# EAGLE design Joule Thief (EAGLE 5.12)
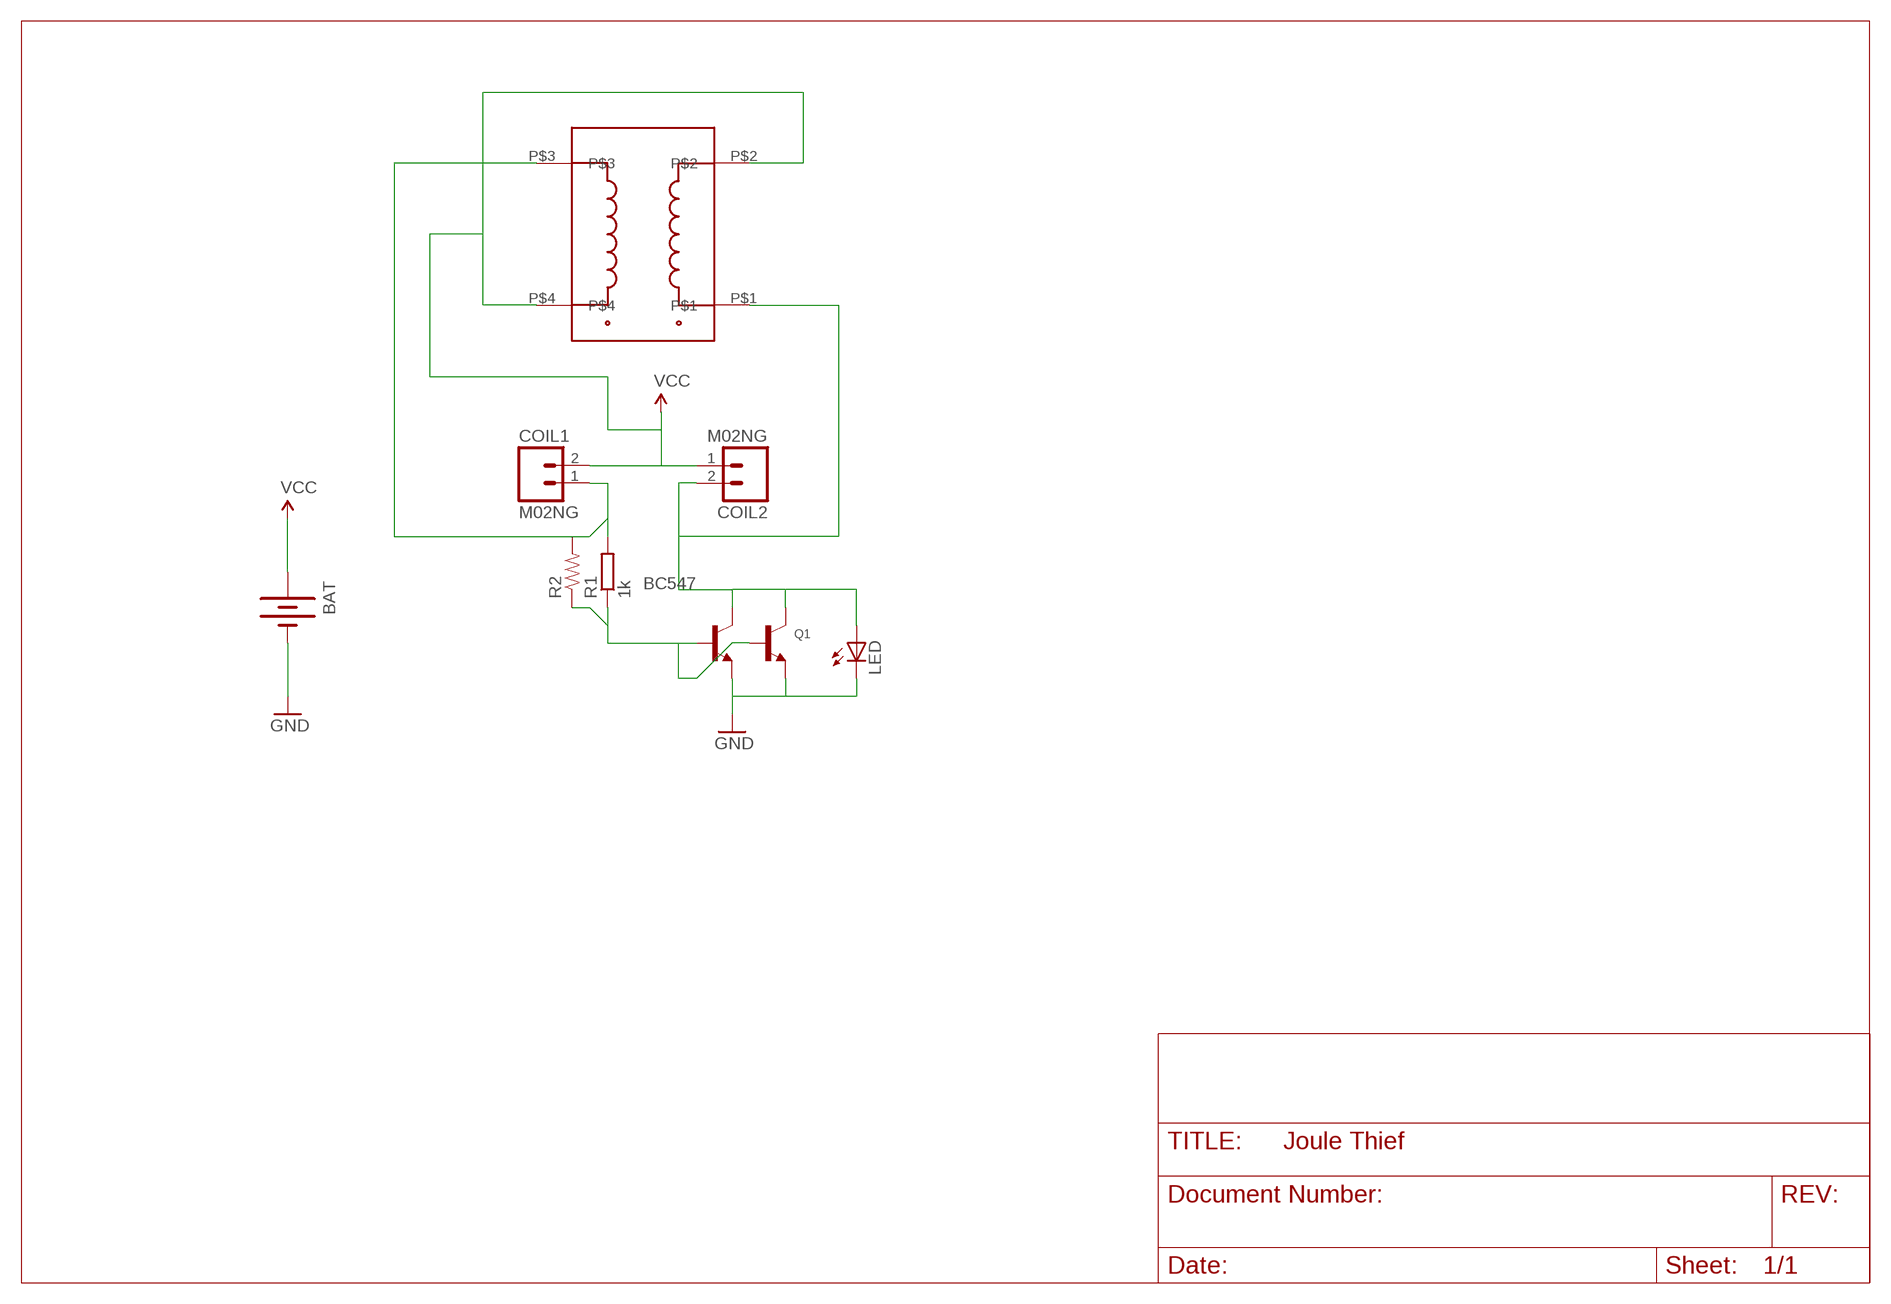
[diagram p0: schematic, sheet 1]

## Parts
BAT  BATTERYAA  [BATTERY-AA]
BC547  BC547-NPN-TO92-CBE  [TO92-CBE]
COIL1  M02NG  [1X02]
COIL2  M02NG  [1X02]
LED  LED5MM  [LED5MM]
Q1  TRANSISTOR_NPNWAVE  [SOT23-W]
R1  1k  R-EU_0309/12  [0309/12]
R2  RESISTOR1206  [1206]
U$1  SRF4532  [SRF4532]

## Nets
GND: BAT.GND@1(-) BC547.E LED.K(C) Q1.2(E)
N$1: BC547.B Q1.1(B) R1.1 R2.1
N$3: BC547.C COIL2.2 LED.A Q1.3(C) U$1.P$1
N$6: COIL1.1 R1.2 R2.2 U$1.P$3
VCC: BAT.PWR@1(+) COIL1.2 COIL2.1 U$1.P$2 U$1.P$4

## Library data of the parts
BAT = SparkFun:BATTERY: Battery Holders
BC547 = transistor:*-NPN-: NPN Transistror BF959 corrected 2008.03.06
COIL1 COIL2 = SparkFun:M02NG
LED = adafruit:LED: LED
Q1 = microbuilder:TRANSISTOR_NPN: NPN Transistor Transistor (NPN) 500mA 45V - BC817 [Digikey: 568-1631-1-ND] Transistor (NPN) 500mA 45V - BC817,215 [Mouser: 771-BC817-T/R] SOT23-R - SOT23 footprint optimised for use with solder paste and reflow ovens. SOT23-W - SOT23 footprint optimised for hand-soldering (larger pads).
R1 = resistor:R-EU_: RESISTOR, European symbol
R2 = SparkFun:RESISTOR: Resistor
U$1 = hackmeisterdk:SRF4532

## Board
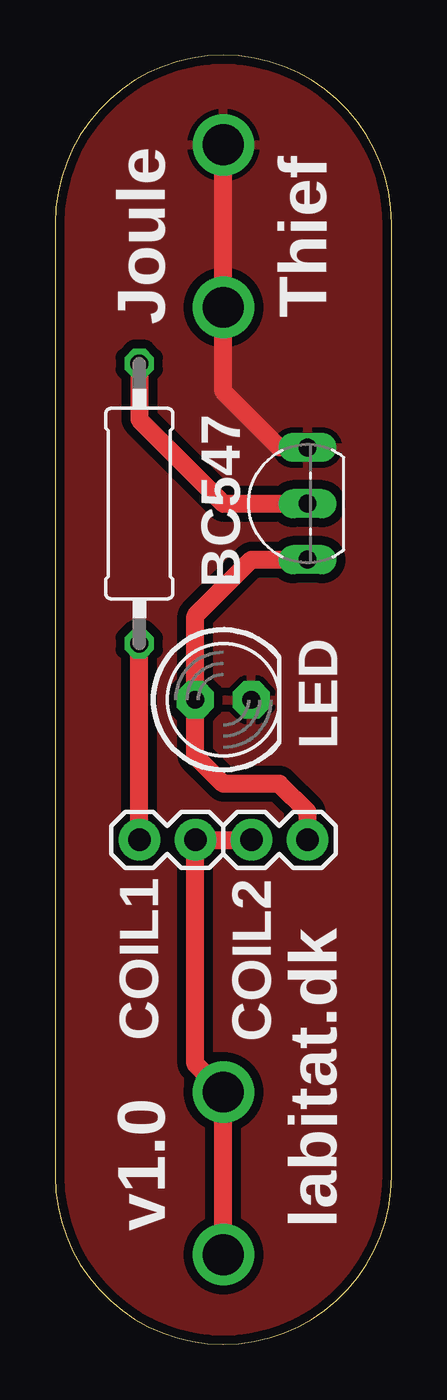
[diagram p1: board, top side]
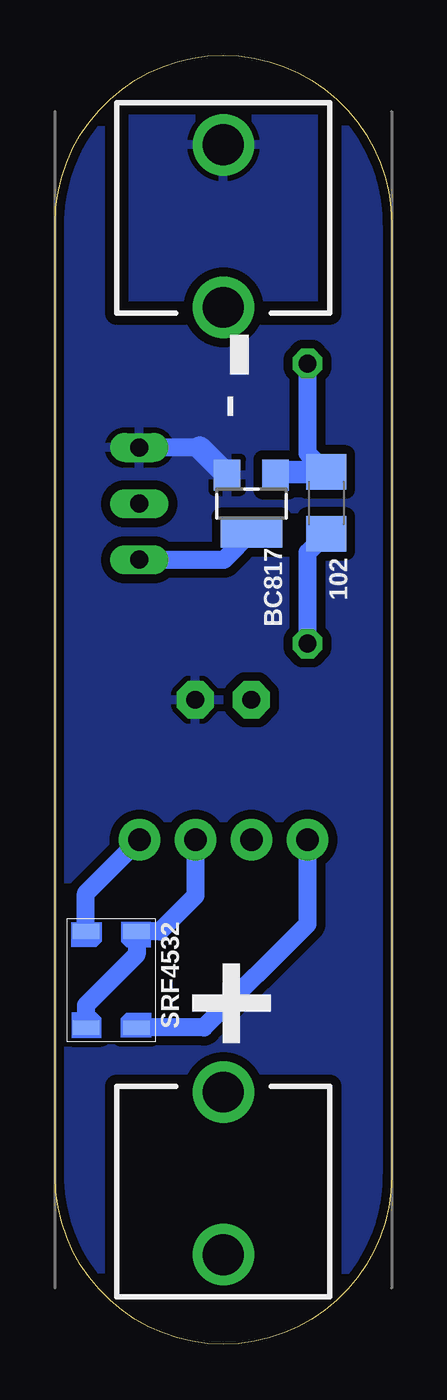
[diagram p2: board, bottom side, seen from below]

Size 15.24 x 58.42 mm. Coordinates in mm from the lower left corner, seen from the top.
Outline: 7.62,0 arc90 15.24,7.62 15.24,50.8 arc90 7.62,58.42 arc90 0,50.8 0,7.62 arc90 7.62,0
Copper layers (1*16): Top 0.035mm / dielectric 1.5mm / Bottom 0.035mm
Design rules "Fusion_eagle_rule_v1.1": minimum track width 6mil, minimum drill 12mil, track to track 6mil, track to pad 6mil, pad to pad 6mil, via to via 6mil, smd to smd 0mil, copper to edge 10mil, drill to drill 10mil, minimum pad ring 10mil, minimum via ring 6mil, stop-mask expansion 2mil, vias tented up to drill 100mil, thermal gap 10mil

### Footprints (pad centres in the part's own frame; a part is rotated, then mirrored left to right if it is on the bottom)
BATTERY-AA = drill 1.854 round: GND@1 25.146,0; GND@2 17.78,0; PWR@1 -25.146,0; PWR@2 -17.78,0
TO92-CBE = drill 0.813 long: B 0,0; C -2.54,0; E 2.54,0
1X02 = drill 1.016 pad 1.88 round: 1 0,0; 2 2.54,0
LED5MM = drill 0.813 pad 1.676 octagon: A -1.27,0; K 1.27,0
SOT23-W = smd 1.2 x 1.4: 1 -1.1,-1.3; 2 1.1,-1.3 | smd 2.8 x 1.4: 3 0,1.3
0309/12 = drill 0.813 octagon: 1 -6.35,0; 2 6.35,0
1206 = smd 1.6 x 1.8: 1 -1.4,0; 2 1.4,0
SRF4532 = smd 0.66 x 1.2: P$1 -2.2,-1.15; P$2 2.15,-1.15; P$3 2.15,1.15; P$4 -2.2,1.15

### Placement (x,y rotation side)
BAT  7.62,29.21 90 bottom
BC547  11.43,38.1 90 top
COIL1  3.81,22.86 0 top
COIL2  8.89,22.86 0 top
LED  7.62,29.21 0 top
Q1  6.35,38.1 180 bottom
R1  3.81,38.1 270 top
R2  2.97,38.13 270 bottom
U$1  12.7,16.51 270 bottom

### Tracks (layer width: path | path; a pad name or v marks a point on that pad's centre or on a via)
GND
  Top 0.813: BC547.E 10.16,40.64 7.62,43.18 BAT.GND@1
  Bottom 0.813: 8.69,40.64 BC547.E
  Bottom 1.016: Q1.2 8.69,40.64
  pour Top (isolate 0.406): 0,50.8 arc-90 7.62,58.42 arc-90 15.24,50.8 15.24,7.62 arc-90 7.62,0 arc-90 0,7.62
  pour Bottom (isolate 0.406): 0,50.8 arc-90 7.62,58.42 arc-90 15.24,50.8 15.24,13.97 15.24,7.62 arc-90 7.62,0 arc-90 0,7.62 0,38.1
N$1
  Top 0.813: BC547.B 7.62,38.1 3.81,41.91 R1.1
  Bottom 0.813: R2.1 3.81,40.38 R1.1
  Bottom 1.016: Q1.1 5.12,39.53 R2.1
N$3
  Top 0.813: COIL2.2 11.43,24.13 10.16,25.4 7.62,25.4 6.35,26.67 LED.A 6.35,33.02 8.89,35.56 BC547.C
  Bottom 0.813: Q1.3 7.59,35.56 BC547.C | U$1.P$1 13.85,20.44 COIL2.2
N$6
  Top 0.813: COIL1.1 R1.2
  Bottom 0.813: R2.2 3.81,35.89 R1.2 | U$1.P$3 8.5,14.36 3.81,19.05 COIL1.1
VCC
  Top 0.813: BAT.PWR@1 7.62,11.43 6.35,12.7 COIL1.2 COIL2.1
  Bottom 0.813: COIL2.1 8.89,20.32 10.5,18.71 U$1.P$4 11.55,17.66 13.85,15.36 U$1.P$2

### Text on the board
bPlace: - | 102 | BC817 | SRF4532 | +
tNames: Thief | Joule | v1.0 | labitat.dk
